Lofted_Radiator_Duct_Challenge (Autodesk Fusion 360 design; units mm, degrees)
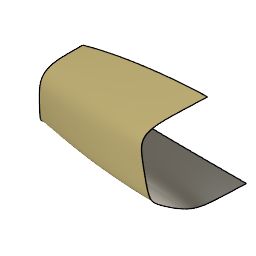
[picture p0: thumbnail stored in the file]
part number: 2026-08-31-12-37-40-158
sketch "Sketch1" plane through (0, 0, 0) normal (0, 1, 0) x axis (1, 0, 0)
  line L1 (0, -100) -> (0, 0)
  line L2 (-70.0208, -100) -> (0, 0)
  curve K1 (-100.0208, -100) -> (-70.0208, -100)
  curve K2 (-208.0646, -93.3918) -> (-100.0208, -100)
  curve K3 (-294.8725, -68.5) -> (-208.0646, -93.3918)
  curve K4 (-294.8725, -68.5) -> (-70.0208, -100)
  curve K5 (-100, 0) -> (0, 0)
  curve K6 (-175, 0) -> (-100, 0)
  curve K7 (-275, -3.5) -> (-175, 0)
  curve K8 (-275, -3.5) -> (0, 0)
  line L3 (-294.8725, -68.5) -> (-275, -3.5)
  point P1 (0, 0)
  point P2 (0, 0)
  point P3 (0, -100)
  point P4 (-70.0208, -100)
  point P10 (-275, -3.5)
  point P7 (-294.8725, -68.5)
  point P8 (-100, 0)
  point P9 (-175, 0)
  point P5 (-100.0208, -100)
  coincident P1 P2
  vertical L1
  horizontal P3 P4
  collinear K5 K6
  horizontal K1
  horizontal K5
  dimension "d1" distance P2 P3 = 100
  dimension "d2" angle L1 L2 = 35
  dimension "d3" distance P2 P10 = 3.5
  dimension "d4" angle L2 L3 = 18
  dimension "d5" distance P7 P10 = 65
  dimension "d6" distance P2 P10 = 275
  dimension "d7" distance P2 P8 = 100
  dimension "d8" distance P8 P9 = 75
  dimension "d9" distance P4 P5 = 30
  dimension "d10" angle K1 K2 = 3.5
  dimension "d11" angle K2 K3 = 12.5
work_plane "WorkPlane1" RotateAngle 80 ExtraOffset 0
sketch "Sketch2" plane through (0, 0, 0) normal (-0.8067, 0.1736, -0.5649) x axis (-0.5736, 0, 0.8192)
  curve K1 (122.0775, -31.091) -> (122.0775, 0)
  curve K2 (122.0775, -62.1821) -> (122.0775, -31.091)
  curve K3 (122.0775, -93.2731) -> (122.0775, -62.1821)
  curve K4 (113.6278, -111.4326) -> (122.0775, -93.2731)
  curve K5 (100.8232, -117.3608) -> (113.6278, -111.4326)
  curve K6 (73.5899, -125.676) -> (100.8232, -117.3608)
  curve K7 (46.1541, -133.7331) -> (73.5899, -125.676)
  curve K8 (37.0684, -133.5725) -> (46.1541, -133.7331)
  curve K9 (30.2304, -127.6943) -> (37.0684, -133.5725)
  curve K10 (17.8528, -111.5942) -> (30.2304, -127.6943)
  curve K11 (0, -84.5744) -> (17.8528, -111.5942)
  curve K12 (0, -62.4154) -> (0, -84.5744)
  curve K13 (0, -31.2077) -> (0, -62.4154)
  curve K14 (0, 0) -> (0, -31.2077)
  curve K15 (0, 0) -> (122.0775, 0)
  point P2 (122.0775, 0)
  point P4 (122.0775, 0)
  point P3 (0, 0)
  point P18 (0, 0)
  coincident P2 P4
  coincident P3 P18
  collinear K13 K14
  collinear K12 K13
  collinear K1 K2
  collinear K2 K3
  equal K1 K2
  equal K2 K3
  equal K13 K14
  vertical K1
  vertical K14
work_plane "WorkPlane2" RotateAngle 90 ExtraOffset 0
sketch "Sketch3" plane through (-250.5141, 0, -76.5898) normal (-0.9563, 0, -0.2924) x axis (-0.2924, 0, 0.9563)
  curve K1 (151.7192, -19.4887) -> (151.7192, 0)
  curve K2 (151.7192, -39.1013) -> (151.7192, -19.4887)
  curve K3 (151.7192, -59.3294) -> (151.7192, -39.1013)
  curve K4 (143.0783, -78.0575) -> (151.7192, -59.3294)
  curve K5 (130.6512, -85.1305) -> (143.0783, -78.0575)
  curve K6 (104.7397, -91.9297) -> (130.6512, -85.1305)
  curve K7 (85.8177, -95.6912) -> (104.7397, -91.9297)
  curve K8 (83.7493, -95.9808) -> (85.8177, -95.6912)
  curve K9 (83.7493, -66.5154) -> (83.7493, -95.9808)
  curve K10 (83.7493, -26.1348) -> (83.7493, -66.5154)
  curve K11 (83.7493, 0) -> (83.7493, -26.1348)
  curve K12 (83.7493, 0) -> (151.7192, 0)
  point P2 (151.7192, 0)
  point P4 (151.7192, 0)
  point P3 (83.7493, 0)
  point P15 (83.7493, 0)
  coincident P2 P4
  coincident P3 P15
  vertical K11
  vertical K1
  collinear K10 K11
  collinear K9 K10
  collinear K1 K2
  collinear K2 K3
sketch "Sketch4" plane through (0, 0, 0) normal (0, 1, 0) x axis (1, 0, 0)
  curve K1 (-293.532, -64.1156) -> (-81.3374, -86.71)
  curve K2 (0, 0) -> (-70.0208, -100)
  curve K3 (-275, -3.5) -> (-294.8725, -68.5)
  curve K4 (-275.5426, -5.2746) -> (-17.1893, 3.2232)
  curve K5 (-102.8621, -87.6869) -> (-59.8127, -85.7331)
  curve K6 (-43.2889, 0.4549) -> (8.9104, 5.9915)
  curve K7 (-277.1074, -10.393) -> (-41.9422, -19.7357)
  curve K8 (-68.3297, -21.3841) -> (-15.5547, -18.0873)
  point P2 (-81.3374, -86.71)
  point P3 (-293.532, -64.1156)
  point P8 (-17.1893, 3.2232)
  point P9 (-275.5426, -5.2746)
  point P14 (-41.9422, -19.7357)
  point P15 (-277.1074, -10.393)
  coincident P2 K2
  coincident P3 K3
  coincident K2 P8
  coincident K3 P9
  midpoint P2 K5
  midpoint P8 K6
  coincident K2 P14
  coincident K3 P15
  midpoint P14 K8
loft "Loft1"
